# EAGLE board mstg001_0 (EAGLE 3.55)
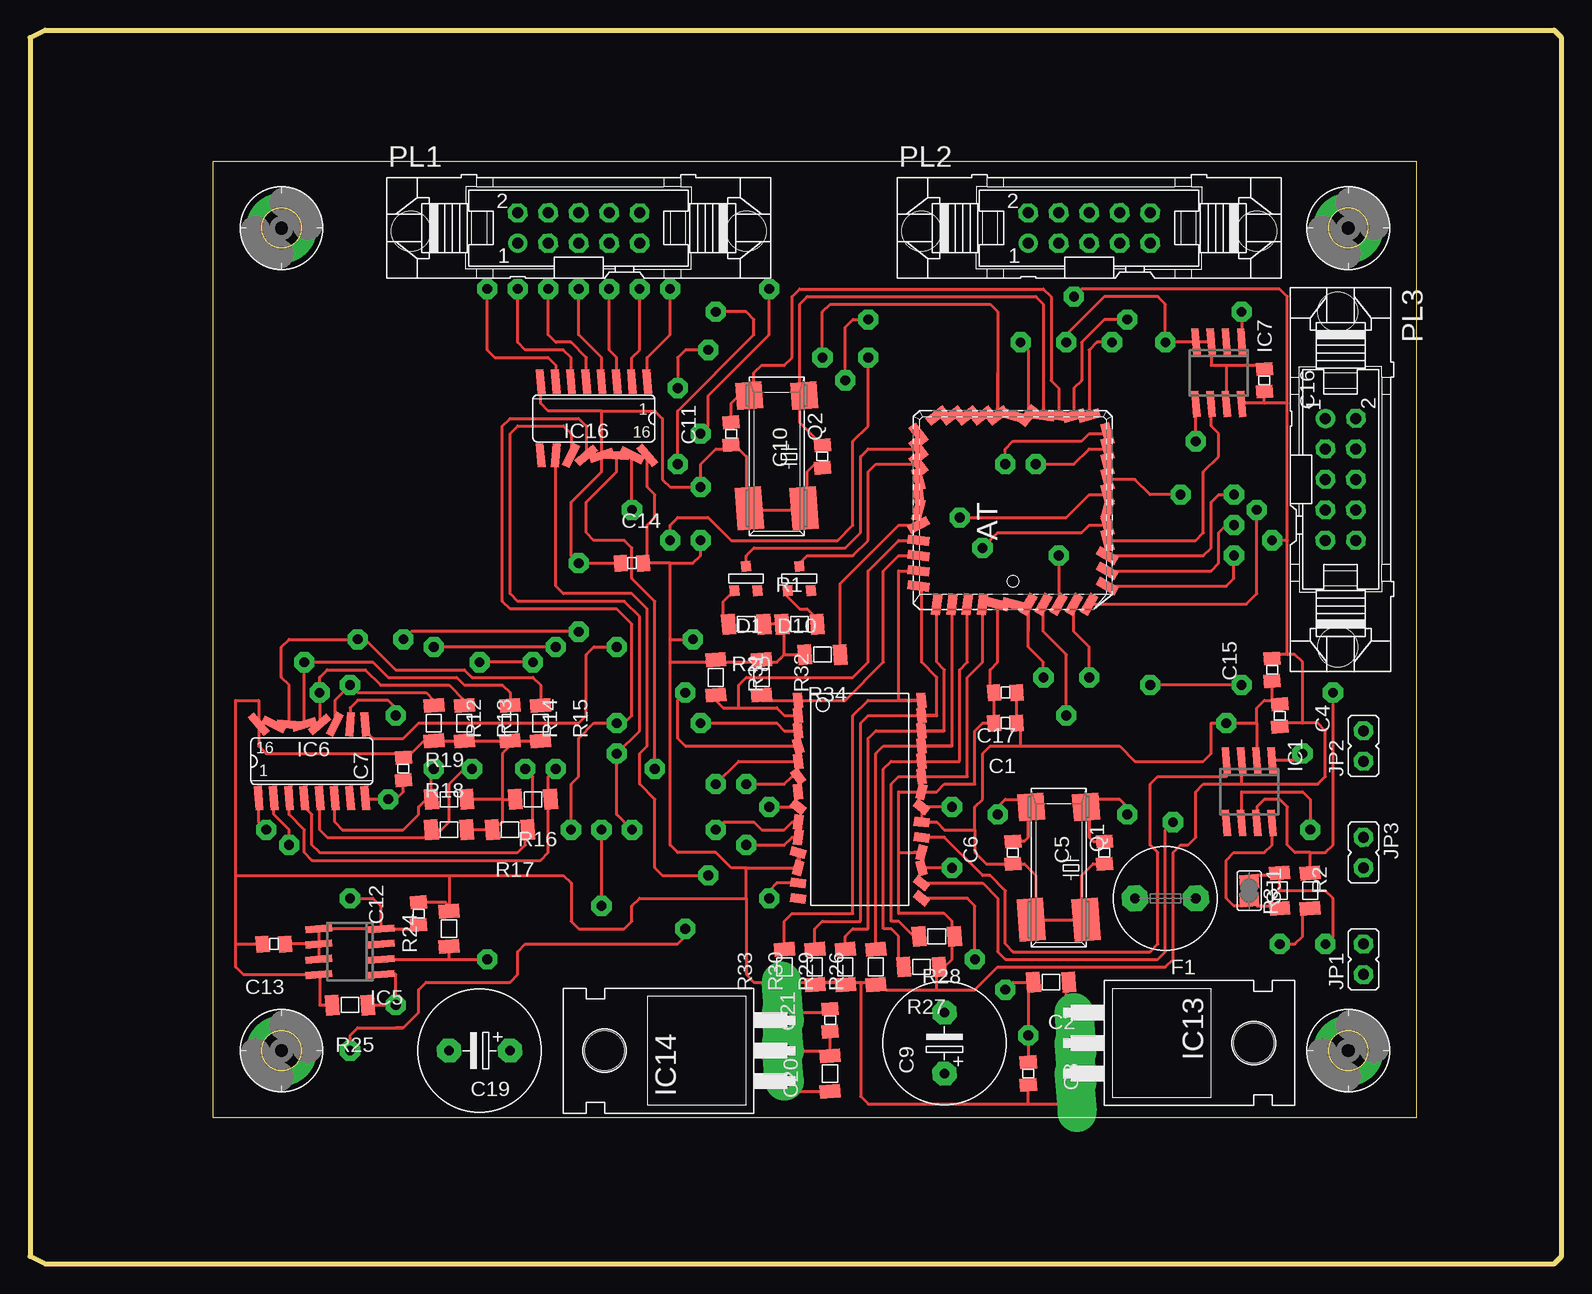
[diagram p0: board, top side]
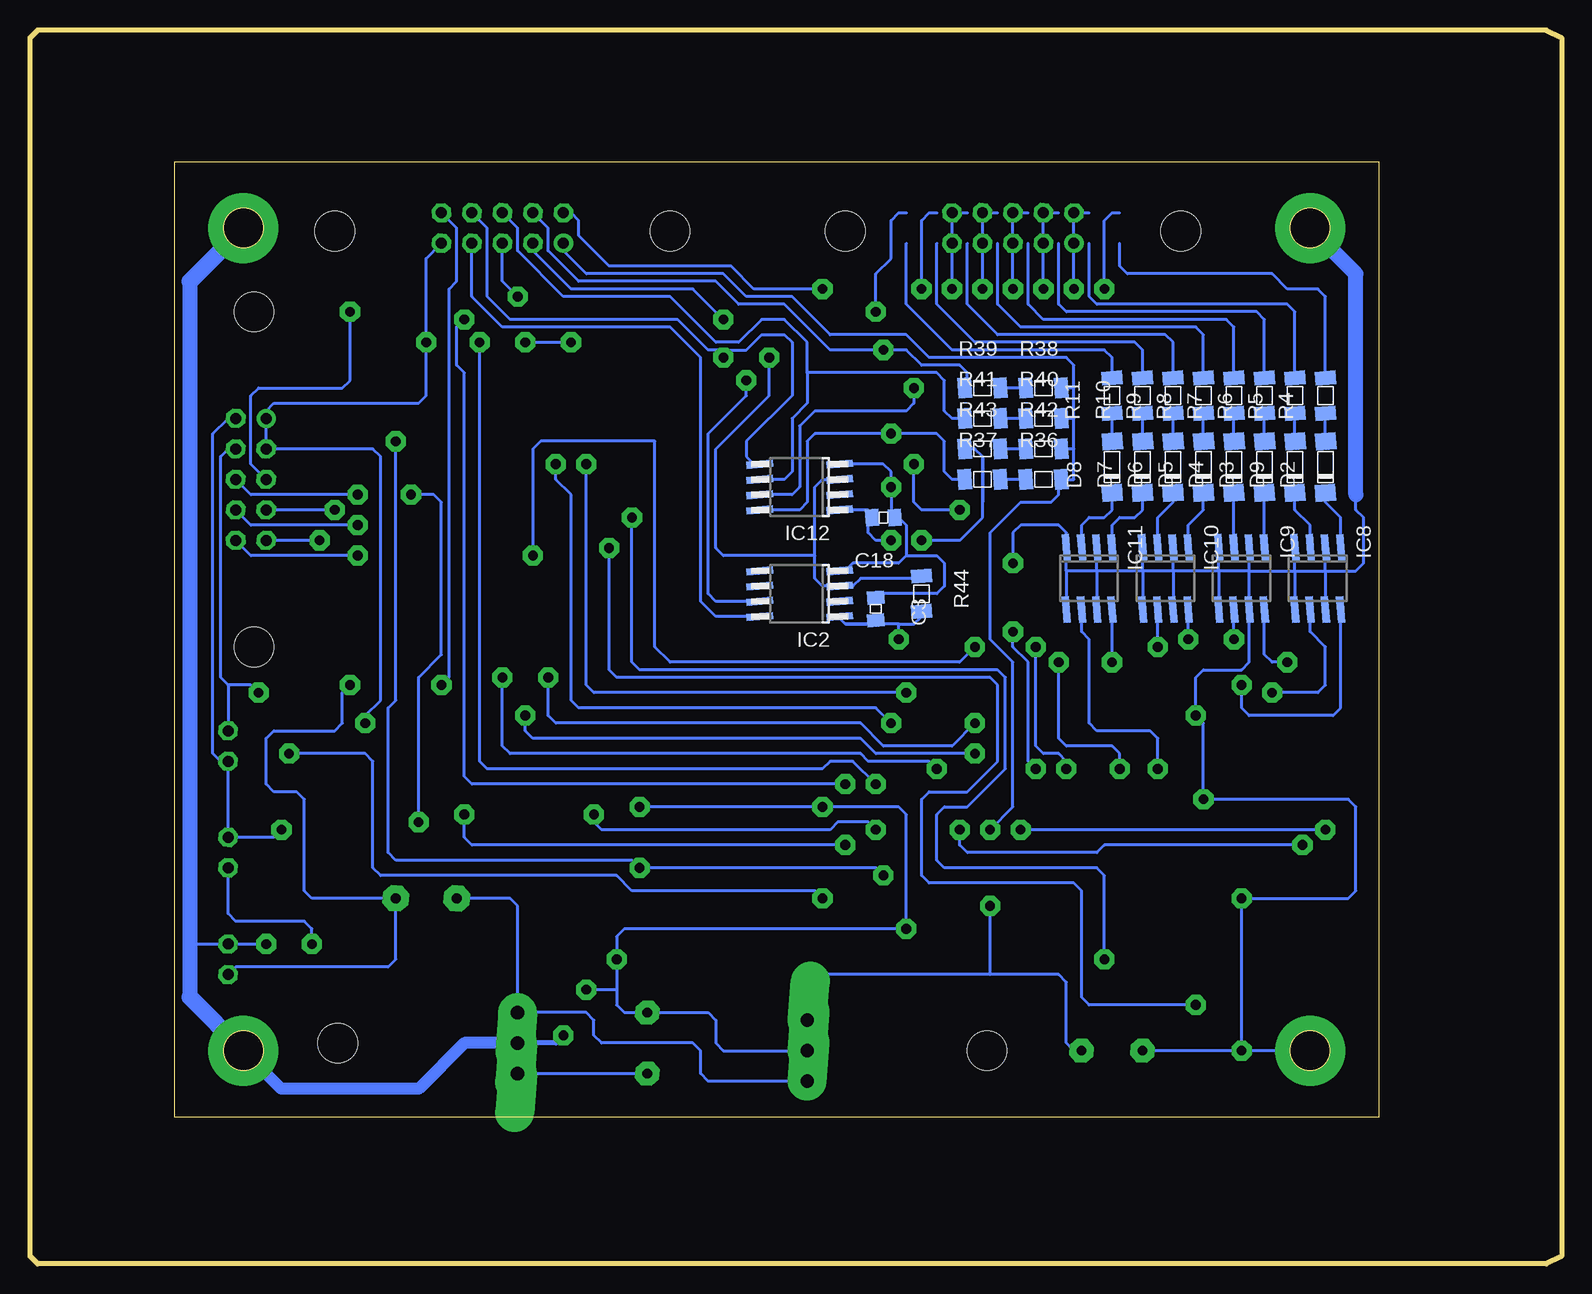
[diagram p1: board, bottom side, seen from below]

Size 127.64 x 102.87 mm. Coordinates in mm from the lower left corner, seen from the top.
Outline: 115.56,12.23 115.56,91.91 15.24,91.91 15.24,12.23 115.56,12.23
Outline: 0,0.63 1.27,0 127,0 127.64,0.63 127.64,102.23 127,102.87 1.27,102.87 0,102.23 0,0.63
Copper layers used: Top, Bottom
vRestrict: area 69.9,50.8 to 94,74.9

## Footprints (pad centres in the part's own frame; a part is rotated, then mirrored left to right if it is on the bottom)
05 = smd 1.092 x 1.397 rotated 4.4:  0.94,0 | smd 1.092 x 1.397 rotated 4.3:  -0.94,0
06 = smd 1.143 x 1.702 rotated 4.4:  1.473,0 | smd 1.143 x 1.702 rotated 4.3:  -1.473,0
-5 = drill 0.813 pad 2.007 octagon:  -2.54,0;  2.54,0
T-23 = smd 0.787 x 0.889 rotated 4.4:  0.991,1.016 | smd 0.787 x 0.889 rotated 4.3:  -0.94,1.016 | smd 0.787 x 0.889 rotated 4.5:  0.025,-1.016
D-80 = smd 1.397 x 1.702 rotated 4.4:  -2.388,0 | smd 1.397 x 1.702 rotated 4.3:  1.905,-0.025
5 = drill 0.813 pad 2.159 octagon:  -2.54,0;  2.54,0
8 = smd 0.6 x 2.2 rotated 4.4:  -0.635,-2.6 | smd 0.6 x 2.2 rotated 4.8:  -0.635,2.6 | smd 0.6 x 2.2 rotated 4.3:  -1.905,-2.6 | smd 0.6 x 2.2 rotated 4.5:  0.635,-2.6 | smd 0.6 x 2.2 rotated 4.6:  1.905,-2.6 | smd 0.6 x 2.2 rotated 4.9:  -1.905,2.6 | smd 0.6 x 2.2 rotated 4.7:  0.635,2.6;  1.905,2.6
8M = smd 0.6 x 2.2 rotated 4.4:  -0.635,-3.33 | smd 0.6 x 2.2 rotated 4.8:  -0.635,3.33 | smd 0.6 x 2.2 rotated 4.3:  -1.905,-3.33 | smd 0.6 x 2.2 rotated 4.5:  0.635,-3.33 | smd 0.6 x 2.2 rotated 4.6:  1.905,-3.33 | smd 0.6 x 2.2 rotated 4.9:  -1.905,3.33 | smd 0.6 x 2.2 rotated 4.7:  0.635,3.33;  1.905,3.33
CC-44 = smd 0.76 x 1.8 rotated 74.5: 0 -1.27,-7.86; 1 1.27,-7.86; 2 2.54,-7.86; 3 3.81,-7.86; 4 5.08,-7.86; 5 6.35,-7.86; N 2.54,7.86 | smd 1.8 x 0.76 rotated 29.5: 0 -7.86,-1.27; 1 -7.86,-2.54; 2 -7.86,-3.81; 3 -7.86,-5.08; 4 -7.86,-6.35 | smd 1.8 x 0.76 rotated 7: 0 -7.86,2.54; 1 -7.86,3.81; 2 -7.86,5.08; 3 -7.86,6.35 | smd 1.8 x 0.76 rotated 52: 0 7.86,1.27; 1 7.86,2.54; 2 7.86,3.81; 3 7.86,5.08; 4 7.86,6.35 | smd 0.76 x 1.8 rotated 7: 4 -6.35,7.86; 5 -5.08,7.86; 6 -3.81,7.86; 7 -2.54,7.86 | smd 0.76 x 1.8 rotated 52: 5 6.35,7.86; 6 5.08,7.86; 7 3.81,7.86 | smd 0.76 x 1.8 rotated 29.5: 5 -6.35,-7.86; 6 -5.08,-7.86; 7 -3.81,-7.86 | smd 1.8 x 0.76 rotated 74.5: 6 7.86,-6.35; 7 7.86,-5.08 | smd 0.76 x 1.8 rotated 275.7: /PR 1.27,7.86 | smd 1.8 x 0.76 rotated 97.7: L1 7.86,-2.54; L2 7.86,-3.81 | smd 0.76 x 1.8 rotated 28.6: VPP -1.27,7.86 | smd 0.76 x 1.8 rotated 74.7:  -2.54,-7.86 | smd 0.76 x 1.8 rotated 74.4:  0,-7.86;  0,7.86 | smd 1.8 x 0.76 rotated 74.4:  -7.86,0;  7.86,0 | smd 1.8 x 0.76 rotated 75.1:  -7.86,1.27 | smd 1.8 x 0.76 rotated 321.2:  7.86,-1.27
-28L = smd 0.762 x 1.27 rotated 321.2: 1 1.27,-5.207; 2 1.27,5.08; 3 8.89,5.08 | smd 0.762 x 1.27 rotated 75.1: 1 0,5.08; 2 5.08,5.08; 3 6.35,-5.207 | smd 0.762 x 1.27 rotated 74.7: / 6.35,5.08 | smd 0.762 x 1.27 rotated 321.4: / 7.62,5.08 | smd 0.762 x 1.27 rotated 275.7: /AS -5.08,-5.207 | smd 0.762 x 1.27 rotated 97.2: E -2.54,-5.207 | smd 0.762 x 1.27 rotated 344.3: E 5.08,-5.207 | smd 0.762 x 1.27 rotated 97.7: L1 2.54,-5.207; L2 3.81,-5.207 | smd 0.762 x 1.27 rotated 275.9: OUT 0,-5.207 | smd 0.762 x 1.27 rotated 95.7:  -7.62,-5.207;  -6.35,-5.207;  -1.27,5.08;  -2.54,5.08;  -3.81,5.08;  -5.08,5.08;  -6.35,5.08;  -7.62,5.08 | smd 0.762 x 1.27 rotated 73.4:  -3.81,-5.207 | smd 0.762 x 1.27 rotated 52.6:  -1.27,-5.207 | smd 0.762 x 1.27 rotated 187.2:  2.54,5.08;  3.81,5.08 | smd 0.762 x 1.27 rotated 187.4:  8.89,-5.207;  7.62,-5.207
16 = smd 0.66 x 2.032 rotated 4.3:  -4.445,-3.073;  3.175,3.073 | smd 0.66 x 2.032 rotated 139.3:  -4.445,3.073 | smd 0.66 x 2.032 rotated 4.4:  -3.175,-3.073 | smd 0.66 x 2.032 rotated 4.5:  -1.905,-3.073 | smd 0.66 x 2.032 rotated 116.8:  -3.175,3.073 | smd 0.66 x 2.032 rotated 94.3:  -1.905,3.073 | smd 0.66 x 2.032 rotated 4.6:  -0.635,-3.073 | smd 0.66 x 2.032 rotated 71.8:  -0.635,3.073 | smd 0.66 x 2.032 rotated 4.7:  0.635,-3.073;  1.905,-3.073 | smd 0.66 x 2.032 rotated 49.3:  0.635,3.073 | smd 0.66 x 2.032 rotated 4.8:  3.175,-3.073 | smd 0.66 x 2.032 rotated 26.8:  1.905,3.073 | smd 0.66 x 2.032 rotated 4.9:  4.445,-3.073 | smd 0.66 x 2.032 rotated 5:  4.445,3.073
220H = drill 1.118 pad 3.251 offset:  -2.54,-10.16;  0,-10.16;  2.54,-10.16 | hole 3.302: 0,4.826
1 = drill 0.914 pad 1.6 octagon:  0,-1.27;  0,1.27
3,3-P = drill 3.302 pad 5.842 round: 3 0,0
V = drill 0.914 pad 1.6 round:  -5.08,-1.27 | drill 0.914 pad 1.6 octagon:  -5.08,1.27;  -2.54,-1.27;  -2.54,1.27;  0,-1.27;  0,1.27;  2.54,-1.27;  2.54,1.27;  5.08,-1.27;  5.08,1.27 | hole 3.302: 13.97,-0.254; -13.97,-0.254
SMX = smd 3.556 x 2.184 rotated 4.4:  4.318,-2.286 | smd 3.556 x 2.184 rotated 4.5:  4.318,2.286 | smd 2.286 x 2.184 rotated 4.3:  -5.08,-2.286 | smd 2.286 x 2.184 rotated 4.6:  -5.08,2.286
 = smd 1.168 x 1.6 rotated 4.3:  -0.762,0 | smd 1.168 x 1.6 rotated 4.4:  0.762,0

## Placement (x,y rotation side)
C1  100n  [05]  81.28,45.08 180 top
C2  330n  [06]  85.09,23.49 180 top
C3  100n  [05]  57.15,54.61 270 bottom
C4  100n  [05]  104.14,45.72 270 top
C5  15pF  [05]  89.53,34.29 90 top
C6  15pF  [05]  81.92,34.29 90 top
C7  100n  [05]  31.12,41.27 90 top
C8  100n  [05]  83.19,15.88 270 top
C9  Elko 470uF  [-5]  76.2,18.41 90 top
C10  30pF +-10pF  [05]  66.04,67.31 90 top
C11  30 pF+-10pF  [05]  58.42,69.22 90 top
C12  100n  [05]  32.39,29.21 90 top
C13  100n  [05]  20.32,26.67 180 top
C14  100n  [05]  50.16,58.42 0 top
C15  100n  [05]  103.5,49.53 90 top
C16  100n  [05]  102.87,73.66 270 top
C17  100n  [05]  81.28,47.62 180 top
C18  100n  [05]  56.52,62.23 180 bottom
C19  Elko 100uF  [-5]  37.47,17.78 180 top
C20  330n  [06]  66.67,15.88 90 top
C21  100n  [05]  66.67,20.32 90 top
D1  rot  [T-23]  59.69,57.15 180 top
D2  SMD4148  [D-80]  19.68,66.67 90 bottom
D3  SMD4148  [D-80]  24.77,66.67 90 bottom
D4  SMD4148  [D-80]  27.3,66.67 90 bottom
D5  SMD4148  [D-80]  29.84,66.67 90 bottom
D6  SMD4148  [D-80]  32.39,66.67 90 bottom
D7  SMD4148  [D-80]  34.92,66.67 90 bottom
D8  SMD4148  [D-80]  37.47,66.67 90 bottom
D9  SMD4148  [D-80]  22.23,66.67 90 bottom
D10  grn  [T-23]  64.13,57.15 180 top
F1  T400mA  [5]  94.61,30.48 180 top
IC1  PCA82C250  [8]  101.6,39.37 180 top
IC2  DS2450  [8M]  63.5,55.88 90 bottom
IC3  AT89S53  [CC-44]  81.92,62.86 90 top
IC4  SJA1000  [-28L]  69.22,39.37 270 top
IC5  DS1621  [8]  26.67,26.04 90 top
IC6  74165  [16]  23.5,41.91 0 top
IC7  MAX700  [8]  99.06,74.3 180 top
IC8  ILD213T  [8]  20.32,57.15 180 bottom
IC9  ILD213T  [8]  26.67,57.15 180 bottom
IC10  ILD213T  [8]  33.02,57.15 180 bottom
IC11  ILD213T  [8]  39.37,57.15 180 bottom
IC12  DS2450  [8M]  63.5,64.77 90 bottom
IC13  78S05  [220H]  97.16,18.41 270 top
IC14  78S10  [220H]  52.7,17.78 90 top
IC16  74HC595  [16]  46.99,70.48 180 top
JP1  2-polig  [1]  111.12,25.4 0 top
JP2  2-polig  [1]  111.12,43.18 0 top
JP3  2-polig  [1]  111.12,34.29 180 top
PAD5  BO3,3P  [3,3-P]  109.86,86.36 0 top
PAD6  BO3,3P  [3,3-P]  20.95,86.36 0 top
PAD7  BO3,3P  [3,3-P]  20.95,17.78 0 top
PAD8  BO3,3P  [3,3-P]  109.86,17.78 0 top
PL1  16V  [V]  45.72,86.36 0 top
PL2  10V  [V]  88.27,86.36 0 top
PL3  10V  [V]  109.22,65.41 270 top
Q1  16MHZ  [SMX]  85.72,33.02 270 top
Q2  16MHZ  [SMX]  62.23,67.31 270 top
R1  2k7  [06]  64.13,53.34 0 top
R2  47k  [06]  104.14,31.11 270 top
R3  120R  [06]  106.68,31.11 90 top
R4  2k7  [06]  19.68,72.39 90 bottom
R5  2k7  [06]  22.23,72.39 90 bottom
R6  2k7  [06]  24.77,72.39 90 bottom
R7  2k7  [06]  27.3,72.39 90 bottom
R8  2k7  [06]  29.84,72.39 90 bottom
R9  2k7  [06]  32.39,72.39 90 bottom
R10  2k7  [06]  34.92,72.39 90 bottom
R11  2k7  [06]  37.47,72.39 90 bottom
R12  4k7  [06]  33.66,45.08 270 top
R13  4k7  [06]  36.2,45.08 270 top
R14  4k7  [06]  40,45.08 270 top
R15  4k7  [06]  42.55,45.08 270 top
R16  4k7  [06]  41.91,38.73 180 top
R17  4k7  [06]  40,36.2 180 top
R18  4k7  [06]  34.92,36.2 0 top
R19  4k7  [06]  34.92,38.73 0 top
R20  2k7  [06]  59.69,53.34 180 top
R24  1k  [06]  34.92,27.94 90 top
R25  1k  [06]  26.67,21.59 180 top
R26  4k7  [06]  70.48,24.77 90 top
R27  4k7  [06]  74.3,24.77 180 top
R28  4k7  [06]  75.56,27.3 180 top
R29  4k7  [06]  67.94,24.77 90 top
R30  4k7  [06]  65.41,24.77 90 top
R31  4k7  [06]  57.15,48.89 270 top
R32  4k7  [06]  60.96,48.89 270 top
R33  4k7  [06]  62.87,24.77 90 top
R34  4k7  [06]  66.04,50.8 180 top
R36  tbd  [06]  43.18,65.41 0 bottom
R37  0R  [06]  48.26,65.41 0 bottom
R38  tbd  [06]  43.18,73.03 0 bottom
R39  0R  [06]  48.26,73.03 0 bottom
R40  tbd  [06]  43.18,70.48 0 bottom
R41  tbd  [06]  48.26,70.48 0 bottom
R42  tbd  [06]  43.18,67.94 0 bottom
R43  tbd  [06]  48.26,67.94 0 bottom
R44  5.0 k  [06]  53.34,55.88 270 bottom
SJ1  SJ  []  101.6,31.11 270 top

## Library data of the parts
C1-C8 C10-C18 C20 C21 D1-D10 R1-R20 R24-R34 R36-R44 = smd
C9 C19 = discrete
F1 = fuse
IC1-IC5 IC7-IC12 = andit4at
IC6 IC16 = andi74sm
IC13 IC14 = linear
JP1-JP3 = jumps
PAD5-PAD8 = holes
PL1-PL3 = pinh-v
Q1 Q2 = quartz
SJ1 = jumper

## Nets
+5V: C1. C3. C4. C7. C8. C9. C12. C13. C14. C15. C16. C17. C18. IC1. IC2. IC3. IC4.1 IC4.2 IC4.3 IC4.E IC5. IC6. IC7. IC12. IC13. IC16. PL2. PL3. R1. R12. R13. R14. R15. R16. R17. R18. R19. R20. R24. R25. R26. R27. R28. R29. R30. R31. R32. R33. R34. R44.
GND: C1. C2. C3. C4. C5. C6. C7. C8. C9. C10. C11. C12. C13. C14. C15. C16. C17. C18. C19. C20. C21. IC1. IC2. IC3. IC4. IC4.1 IC4.2 IC4.3 IC5. IC6. IC7. IC8. IC9. IC10. IC11. IC12. IC13. IC14. IC16. JP1. PAD5.3 PAD6.3 PAD7.3 PAD8.3 PL2. PL3. Q1. Q2. R2. SJ1.
N$1: IC3.0 IC4. R28.
N$2: IC3.1 IC4. R27.
N$3: IC3.5 IC4. R33.
N$4: IC3.VPP R34.
N$5: IC3.7 IC4. R31.
N$6: C2. C20. F1. IC13. IC14.
N$7: IC12. PL2. R37.
N$9: IC1. IC4.
N$11: C11. IC3.L2 Q2.
N$12: C19. C21. IC14. PL2. R36. R38. R40. R42.
N$15: IC16. PL1.
N$16: IC1. JP2. PL3. R3.
N$18: PL1. R5.
N$19: IC2. IC3.0 IC12. R44.
N$20: IC16. PL1.
N$21: PL1. R4.
N$22: D10. IC3.7
N$23: D1. IC3.6
N$24: D10. R1.
N$26: PL1. R6.
N$27: D9. R5.
N$28: D2. R4.
N$29: IC3.0 IC6. IC16.
N$30: IC3.1 IC6. IC16.
N$31: D3. R6.
N$32: D4. R7.
N$33: D5. R8.
N$34: IC3.2 IC6.
N$35: D6. R9.
N$36: IC1. JP2. JP3. PL3.
N$37: IC3.4 IC4./AS
N$38: IC3.6 PL3.
N$39: IC3.5 PL3.
N$40: IC3.7 PL3.
N$41: IC3. IC7.
N$42: IC3.5 IC4.
N$43: IC16. PL1.
N$44: IC3.1 IC5. R24.
N$45: IC3.0 IC5. R25.
N$46: IC3.6 IC4.E
N$47: IC3.7 IC4.
N$48: IC3.2 IC4./
N$49: IC7. PL3.
N$50: IC4./ IC7. IC16.
N$51: C5. IC4.L2 Q1.
N$52: C6. IC4.L1 Q1.
N$54: D1. R20.
N$55: IC1. IC4.
N$56: R36. R37.
N$57: R38. R39.
N$58: R40. R41.
N$59: R42. R43.
N$60: IC2. PL2.
N$61: F1. JP1. PL2.
N$63: IC1. R2. SJ1.
N$64: D7. R10.
N$65: JP3. R3.
N$67: D8. R11.
N$68: D9. IC8.
N$69: IC12. PL2. R39.
N$70: C10. IC3.L1 Q2.
N$71: D3. IC9.
N$72: D4. IC9.
N$73: D5. IC10.
N$74: D6. IC10.
N$75: D7. IC11.
N$76: IC6. IC8. R12.
N$77: D8. IC11.
N$78: IC2. PL2.
N$79: IC3.4 PL3.
N$80: IC6. IC8. R13.
N$81: IC12. PL2. R41.
N$82: D2. IC8.
N$83: IC6. IC9. R14.
N$84: IC16. PL1.
N$85: IC6. IC9. R15.
N$86: IC12. PL2. R43.
N$87: IC6. IC10. R16.
N$88: IC16. PL1.
N$89: IC6. IC10. R17.
N$90: IC16. PL1.
N$91: IC6. IC11. R18.
N$92: IC16. PL1.
N$93: IC6. IC11. R19.
N$94: IC16. PL1.
N$95: PL1. R11.
N$96: PL1. R8.
N$98: IC3.3 IC16.
N$102: IC3.2 IC4. R26.
N$104: IC3.3 IC4. R29.
N$105: IC3.4 IC4. R30.
N$106: IC3.6 IC4. R32.
N$108: PL1. R7.
N$110: PL1. R9.
N$112: PL1. R10.

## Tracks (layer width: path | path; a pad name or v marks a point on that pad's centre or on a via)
+5V  (via drill 0.81 pad 1.68)
  Top 0.254: 17.14,32.38 17.14,46.99 19.05,46.99 19.05,44.98 19.05,43.18 19.68,42.55 31.12,42.55 | 102.87,71.75 102.87,72.72 102.87,73.03 | 104.78,71.75 104.78,80.64 104.14,81.28 87.63,81.28 v87,80.64 | 104.78,71.75 102.87,71.75 | 104.78,60.33 104.78,71.75 | 65.41,23.49 63.07,23.49 R33. 62.87,23.49 60.33,23.49 59.69,24.13 59.69,30.48 | 67.94,23.49 R29. 68.15,23.49 70.48,23.49 R26. 70.69,23.49 71.32,22.86 75.56,22.86 | R30. 65.61,23.49 66.04,23.49 | 67.94,23.49 66.04,23.49 | 73.66,34.29 74.3,34.29 72.39,34.29 | 64.13,33.15 IC4.3 | 64.13,33.15 64.13,34.29 | 72.39,34.29 72.39,39.37 IC4.1 75.56,39.37 76.2,40 78.74,40 78.74,44.45 79.38,45.08 80.34,45.08 80.01,45.08 80.34,45.42 80.34,47.62 80.01,47.62 80.01,49.53 80.64,50.17 80.64,55 | 72.39,34.29 72.39,29.21 76.2,29.21 76.84,28.57 76.84,27.3 | 77.47,27.3 R28. 76.84,27.3 | 40.21,43.61 42.55,43.61 42.55,43.81 | 40.21,43.61 40,43.81 40,43.61 36.4,43.61 36.2,43.81 36.2,43.61 33.86,43.61 33.66,43.81 33.66,43.61 32.82,43.61 31.75,42.55 31.12,42.55 | 67.94,23.49 69.22,23.49 69.22,13.97 69.85,13.33 83.19,13.33 | 65.41,23.49 67.94,23.49 | IC4.E 64.01,33.15 64.13,33.02 | 59.69,33.02 64.13,33.02 | 103.5,50.47 103.5,50.8 104.78,50.8 | 104.14,44.78 104.14,45.08 106.05,45.08 | 106.05,45.08 107.31,45.08 107.95,44.45 107.95,40.64 107.31,40 100.97,40 | 106.05,45.08 106.05,50.17 105.41,50.8 104.78,50.8 | R32. 60.96,50.17 57.15,50.17 | 53.34,50.17 53.34,34.92 53.98,34.29 57.15,34.29 58.42,33.02 59.69,33.02 | 100.97,40 97.79,40 97.16,39.37 97.16,35.56 96.52,34.92 95.89,34.92 95.25,34.29 95.25,25.4 94.61,24.77 80.64,24.77 78.74,22.86 75.56,22.86
  Top 0.254: 75.56,22.86 75.56,24.77 R27. 76.2,24.77 76.84,25.4 76.84,27.3 | 53.34,50.17 57.15,50.17 | 57.15,50.8 R31. 57.15,50.17 | 65.41,23.49 66.04,23.49 | 64.13,33.02 64.13,33.15 | 40.21,43.61 40.21,43.38 39.37,42.55 39.37,38.73 | 40.64,38.73 40.44,38.73 39.37,38.73 | 39.37,38.73 36.4,38.73 | 34.92,29.21 34.92,29.41 34.92,29.84 | 100.97,40 100.97,41.97 | 32.39,30.15 34.62,30.15 34.92,29.84 | 104.78,50.8 104.78,60.33 | 104.78,60.33 v103.5,60.33 | 62.87,53.34 R1. R20. | 62.87,50.8 62.43,50.37 | 100.97,71.75 100.97,72.39 | 100.97,71.12 100.97,71.69 100.97,71.75 | 102.87,71.75 100.97,71.75 | 34.92,32.38 34.92,29.84 | 17.14,32.38 34.92,32.38 | 17.14,26.67 17.14,24.77 17.78,24.13 24.07,24.13 24.13,24.13 24.13,21.59 25.2,21.59 | 19.68,26.67 19.38,26.67 17.14,26.67 | 17.14,26.67 17.14,32.38 | 53.34,58.42 55.24,58.42 55.88,59.05 v55.88,60.33 | 53.34,52.07 53.34,58.42 | 62.87,50.8 64.57,50.8 | 83.19,13.33 83.19,14.93 | 83.19,13.33 86.36,13.33 87,13.97 IC13. | 51.44,67.41 51.44,64.77 52.07,64.14 52.07,62.23 51.44,61.59 51.44,58.42 | 51.44,58.42 51.1,58.42 | 53.34,58.42 51.44,58.42 | 34.92,32.38 44.45,32.38 45.09,31.75 45.09,28.57 45.72,27.94 49.53,27.94 50.16,28.57 50.16,29.84 50.8,30.48 59.69,30.48 | 59.69,30.48 59.69,33.02 | 31.12,42.55 31.12,42.22 | 39.37,38.73 39.37,36.83 38.73,36.2 | 38.73,36.2 38.53,36.2 | 38.73,36.2 36.4,36.2 | R20. 60.96,53.34 | 62.87,53.34 R20. | 62.87,50.8 62.87,53.34 | 62.87,50.8 62.23,50.17 53.34,50.17 | 53.34,50.17 53.34,52.07 | 53.34,52.07 v55.24,52.07
  Bottom 0.254: v103.5,60.33 107.95,60.33 | 88.27,85.09 88.27,81.92 v87,80.64 | 60.17,53.97 60.17,53.82 59.69,53.34 | 59.69,53.34 57.78,53.34 57.15,53.97 57.15,53.67 57.15,53.34 | 53.34,54.41 53.34,53.97 53.98,53.34 55.24,53.34 | 85.72,15.88 IC13. 76.2,15.88 | v55.88,60.33 57.15,60.33 57.78,60.96 57.78,62.23 57.45,62.23 57.15,62.23 57.78,62.86 60.17,62.86 | 57.15,53.34 59.69,53.34 | 55.24,53.34 57.15,53.34 | v55.24,52.07 55.24,53.34
GND  (via drill 0.81 pad 1.68)
  Top 0.254: v61.59,38.1 64.01,38.1 | v76.84,38.1 IC4.2 74.3,36.83 75.56,36.83 76.2,36.2 78.74,36.2 | v78.74,25.4 78.74,29.84 78.1,30.48 74.3,30.48 | 104.14,32.38 104.14,31.11 107.95,31.11 108.58,30.48 108.58,27.3 v107.95,26.67 | 104.14,32.38 102.23,32.38 101.6,31.75 101.6,31.88 | C10. 66.04,66.67 65.41,66.67 64.77,66.04 64.77,62.86 | 64.77,62.86 64.77,62.23 | 59.69,62.86 64.39,62.86 64.52,62.99 64.64,62.99 64.77,62.86 | 59.94,62.99 59.82,62.86 59.69,62.86 | 59.69,62.86 59.69,67.31 59.05,67.94 | 88.01,28.7 83.44,28.7 83.69,28.7 83.82,28.57 83.82,32.38 82.86,33.35 82.22,33.35 81.92,33.66 C6. 79.68,33.35 78.74,34.29 78.74,36.2 | 88.01,28.7 88.14,28.7 88.27,28.57 | 88.01,28.7 87.76,28.7 87.63,28.57 87.63,32.38 88.59,33.35 89.23,33.35 89.53,33.66 C5. | 102.23,45.08 v99.69,45.08 98.42,45.08 98.42,42.55 97.79,41.91 92.08,41.91 90.81,43.18 82.55,43.18 | 102.23,45.08 102.23,46.36 102.87,46.99 103.5,46.99 | 82.55,45.08 82.22,45.42 82.22,47.32 81.92,47.62 C17. | 78.74,36.2 78.74,38.1 79.38,38.73 79.38,42.55 80.01,43.18 82.55,43.18 | 82.55,43.18 82.55,45.08 | 42.55,73.56 42.55,71.75 43.18,71.12 47.62,71.12 | 47.62,71.12 47.62,67.41 47.62,66.04 45.09,63.5 45.09,59.05 v45.72,58.42 C14. | 47.62,71.12 52.07,71.12 52.7,70.48 52.7,65.41 53.34,64.77 v55.88,64.77 55.88,66.67 57.15,67.94 59.05,67.94 | 59.05,67.94 58.42,67.94 C11. 58.42,68.58 | 27.94,38.84 27.94,38.73 v29.84,38.73 30.48,38.73 31.12,39.37 C7. | 26.67,44.98 26.67,46.36 27.3,46.99 29.84,46.99 30.48,46.36 v30.48,45.72 | 24.07,25.4 24.07,26.61 24.13,26.67 | 24.13,26.67 24.07,26.67 C13. 20.95,26.67 | 24.13,26.67 24.07,26.73 IC5. 29.21,27.94
  Top 0.254: 29.21,27.94 29.27,27.94 31.75,27.94 32.39,28.57 C12. 32.39,27.94 29.21,27.94 | 81.92,45.08 C1. 82.55,45.08 | 103.5,46.99 C15. | 103.5,46.99 104.14,46.36 C4. | 102.23,41.91 102.23,41.97 102.23,45.08 | 83.19,16.51 C8. v83.19,19.05 83.19,22.86 83.82,23.49 83.19,23.49 | 66.67,17.14 66.67,17.35 66.67,17.78 | 66.67,17.78 C21. | 62.87,17.78 66.67,17.78 | 99.69,74.93 98.42,74.93 98.42,76.84 | 98.42,76.84 98.36,76.89 97.16,76.89 95.31,76.89 95.25,76.84 v94.61,76.84 94.61,80.01 93.98,80.64 89.53,80.64 86.36,77.47 v86.36,76.84 | 99.69,74.93 99.69,71.69 | C16. 102.87,74.3 102.23,74.93 99.69,74.93 | 98.42,76.84 98.42,76.89 | 104.14,32.38 R2. | v26.67,30.48 28.57,30.48 29.21,29.84 29.21,27.94 | 83.19,70.72 83.19,76.2 v82.55,76.84 | 83.19,23.49 81.92,23.49 v81.28,22.86 | 83.19,23.49 83.62,23.49 | v54.61,27.94 54.61,27.3 53.98,26.67 41.27,26.67 40.64,26.04 40.64,24.13 40,23.49 33.02,23.49 32.39,22.86 32.39,20.95 31.12,19.68 | 31.12,19.68 30.48,19.68 | 31.12,19.68 27.3,19.68 26.67,19.05 v26.67,17.78
  Bottom 0.254: v76.84,38.1 v61.59,38.1 55.24,38.1 54.61,37.47 v54.61,27.94 78.1,27.94 78.74,27.3 v78.74,25.4 78.74,22.86 | v107.95,26.67 JP1. 114.3,26.67 | 22.23,57.78 22.23,59.75 | 26.04,57.78 26.04,59.75 | 28.57,57.78 28.57,59.75 | 32.39,57.78 32.39,59.75 | 34.92,57.78 34.92,59.75 | 38.73,57.78 38.73,59.75 | 41.27,57.78 41.27,59.75 41.27,60.96 41.91,61.59 45.09,61.59 45.72,60.96 v45.72,58.42 | 19.68,57.78 19.68,54.55 | 22.23,57.78 19.68,57.78 | 22.23,57.78 IC8. | 26.04,57.78 22.23,57.78 | 26.04,57.78 26.04,54.55 26.04,50.17 26.67,49.53 29.84,49.53 30.48,48.89 v30.48,45.72 29.84,45.08 v29.84,38.73 17.78,38.73 17.14,38.1 17.14,31.11 17.78,30.48 v26.67,30.48 v26.67,17.78 | 26.04,57.78 28.57,57.78 | 28.57,57.78 IC9. | 28.57,57.78 32.39,57.78 | 32.39,57.78 32.39,54.55 | 32.39,57.78 34.92,57.78 | 34.92,57.78 IC10. | 34.92,57.78 38.73,57.78 | 38.73,57.78 38.73,54.55 | 38.73,57.78 41.27,57.78 | 41.27,57.78 IC11. | 78.74,22.86 78.74,21.59 78.1,20.95 C9. 71.12,20.95 70.48,20.32 70.48,18.41 69.85,17.78 62.87,17.78 | 93.34,85.09 94.61,83.82 v94.61,76.84 94.61,72.39 95.25,71.75 107.31,71.75 107.95,71.12 107.95,70.48 107.95,67.94 99.06,67.94 98.42,67.31 98.42,46.99 99.69,45.72 v99.69,45.08 | PAD7.3 v26.67,17.78 | 60.17,57.78 59.69,57.78 59.05,58.42 55.24,58.42 54.61,59.05 | 60.17,66.67 56.52,66.67 55.88,66.04 v55.88,64.77 55.88,62.23 C18. 55.24,62.23 54.61,61.59 54.61,59.05 | 60.17,66.67 60.33,66.67 | C3. 57.15,55.88 52.07,55.88 51.44,56.52 51.44,58.42 52.07,59.05 54.61,59.05 | 19.68,57.78 19.68,59.75 | 19.68,57.78 17.14,57.78 16.51,58.42 16.51,62.23 17.14,62.86 17.14,64.14 | v86.36,76.84 v82.55,76.84
  Bottom 0.254: 78.74,22.86 v81.28,22.86 | 60.17,66.67 60.17,66.52 | v26.67,17.78 C19.
  Bottom 0.406: v83.19,19.05 83.82,18.41 87,18.41
  Bottom 1.016: 87,18.41 91.44,18.41 95.25,14.6 106.68,14.6 PAD8.3
  Bottom 1.27: 114.3,81.92 114.3,26.67 114.3,22.23 | PAD6.3 17.14,82.55 17.14,64.14
  Bottom 1.422: PAD8.3 114.3,22.23 | 114.3,81.92 PAD5.3
N$1
  Top 0.254: 79.38,55 79.38,50.17 78.1,48.89 78.1,40.64 74.3,40.64 72.39,40.64 71.75,40 71.75,28.57 72.39,28.57 73.66,27.3 74.09,27.3
N$2
  Top 0.254: 78.1,55 78.1,50.17 77.47,49.53 77.47,41.91 74.3,41.91 71.75,41.91 71.12,41.27 71.12,27.94 71.75,27.94 72.39,27.3 72.39,25.4 73.03,24.77 72.82,24.77
N$3
  Top 0.254: 74.06,57.78 72.39,57.78 72.39,46.99 IC4. 69.85,46.99 68.58,45.72 68.58,29.21 63.5,29.21 62.87,28.57 62.87,26.24 62.87,26.04
N$4
  Top 0.254: R34. 67.51,56.72 72.39,61.59 IC3.VPP 74.3,61.59
N$5
  Top 0.254: 74.06,60.33 72.39,60.33 69.85,57.78 69.85,50.17 68.58,48.89 59.69,48.89 59.05,48.26 59.05,46.36 | 59.05,46.36 62.23,46.36 62.87,45.72 64.01,45.72 64.13,45.72 | 57.15,47.42 57.15,46.99 57.78,46.36 59.05,46.36
N$6
  Top 0.254: 86.36,20.95 87,20.95 86.36,21.59 86.36,23.49 C2. | C20. 63.7,14.4 62.87,15.24
  Bottom 0.254: F1. 87.63,30.48 87,29.84 87,20.95 | 62.87,15.24 71.12,15.24 71.75,15.88 71.75,17.78 72.39,18.41 80.01,18.41 80.64,19.05 80.64,20.32 81.28,20.95 87,20.95 | 87,20.95 86.36,20.95
N$7  (via drill 0.81 pad 1.68)
  Top 0.254: v55.88,69.22 56.52,69.85 56.52,72.39 61.59,77.47 v61.59,81.28
  Bottom 0.254: 83.19,87.63 82.55,87.63 81.92,87 81.92,85.73 79.38,83.19 69.22,83.19 67.31,81.28 v61.59,81.28 | 49.53,65.41 R37. 50.8,65.41 51.44,66.04 51.44,68.58 52.07,69.22 v55.88,69.22 62.23,69.22 62.87,68.58 62.87,63.5 63.5,62.86 66.83,62.86
N$9  (via drill 0.81 pad 1.68)
  Top 0.254: 103.5,41.97 105.47,41.97 v106.05,42.55 | 64.01,31.75 62.23,31.75 61.59,31.11 v61.59,30.48
  Bottom 0.254: v106.05,42.55 99.69,42.55 99.06,41.91 99.06,33.02 98.42,32.38 78.74,32.38 77.47,31.11 62.23,31.11 v61.59,30.48
N$11
  Top 0.254: 59.05,72.39 59.94,72.39 | 59.05,72.39 60.33,73.66 60.33,74.3 60.96,74.93 62.87,74.93 63.5,75.56 63.5,80.64 64.13,81.28 84.45,81.28 85.09,80.64 85.09,73.66 85.72,73.03 IC3.L2 | 59.05,72.39 58.42,71.75 58.42,70.16 58.42,69.85
N$12  (via drill 0.81 pad 1.68)
  Top 0.254: IC14. 63.5,20.95 66.04,20.95 66.67,21.59 66.67,21.26 | v47.62,29.84 v47.62,36.2
  Bottom 0.254: 40,17.78 40.64,17.78 41.27,18.41 41.27,23.49 41.91,24.13 47.62,24.13 | 47.62,24.13 61.59,24.13 62.87,22.86 IC14. | 40.64,70.48 40.64,73.03 | 83.19,85.09 83.19,84.45 81.28,82.55 69.85,82.55 67.94,80.64 64.13,80.64 60.96,77.47 54.61,77.47 52.7,75.56 41.27,75.56 40.64,74.93 40.64,73.03 | 40.64,70.48 41.71,70.48 | 40.64,67.94 40.64,70.48 | 41.91,67.94 41.71,67.94 40.64,67.94 | 40.64,67.94 40.64,65.41 41.71,65.41 41.91,65.41 41.91,64.14 42.55,63.5 45.09,63.5 47.62,60.96 47.62,52.07 45.72,50.17 45.72,38.1 v47.62,36.2 | 47.62,24.13 v47.62,29.84 | 40.64,73.03 41.71,73.03
N$15  (via drill 0.81 pad 1.68)
  Top 0.254: v57.15,79.38 59.69,79.38 60.33,78.74 60.33,77.47 53.98,71.12 v53.98,66.67 | v50.16,62.86 50.16,67.41
  Bottom 0.254: 54.61,87.63 55.24,87.63 55.88,87 55.88,83.82 57.15,82.55 v57.15,79.38 | v53.98,66.67 53.98,63.5 53.34,62.86 v50.16,62.86
N$16  (via drill 0.81 pad 1.68)
  Top 0.254: 106.68,32.38 106.68,32.59 106.68,34.29 | 106.68,34.29 107.95,34.29 108.58,34.92 v108.58,47.62 | 106.68,34.29 105.41,34.29 104.78,34.92 104.78,38.1 104.14,38.73 102.87,38.73 102.23,38.1 102.23,36.77
  Bottom 0.254: 110.49,67.94 111.12,67.94 111.76,67.31 111.76,48.89 111.12,48.26 | 111.12,48.26 JP2. | v108.58,47.62 109.22,48.26 111.12,48.26
N$18
  Bottom 0.254: 39.37,85.09 39.37,80.64 38.73,80.01 22.86,80.01 22.23,79.38 22.23,73.86 22.23,73.66
N$19  (via drill 0.81 pad 1.68)
  Top 0.254: 80.64,74.3 IC3.0 80.64,79.38 80.01,80.01 66.67,80.01 66.04,79.38 v66.04,75.56
  Bottom 0.254: R44. 53.34,57.15 58.42,57.15 59.05,56.52 60.17,56.52 61.59,56.52 62.23,57.15 62.23,59.05 | 59.69,65.41 60.17,65.41 61.59,65.41 62.23,64.77 62.23,59.05 | 62.23,59.05 69.85,59.05 70.48,59.69 70.48,67.94 66.04,72.39 v66.04,75.56
N$20  (via drill 0.81 pad 1.68)
  Top 0.254: 51.44,73.56 51.44,75.56 53.34,77.47 v53.34,81.28
  Bottom 0.254: 52.07,87.63 52.7,87.63 53.34,87 v53.34,81.28
N$21
  Bottom 0.254: 36.83,85.09 36.83,83.19 36.2,82.55 24.13,82.55 22.86,81.28 20.32,81.28 19.68,80.64 19.68,73.86 19.68,73.66
N$22
  Top 0.254: D10. 64.11,58.39 64.77,59.05 68.58,59.05 69.85,60.33 69.85,66.04 70.48,66.67 74.06,66.67 74.3,66.67
N$23
  Top 0.254: 74.06,67.94 69.85,67.94 69.22,67.31 69.22,60.96 67.94,59.69 60.33,59.69 59.69,59.05 59.69,58.42 59.66,58.39 D1.
N$24
  Top 0.254: 63.14,56.13 63.14,55.6 64.13,54.61 64.77,54.61 65.41,53.97 65.41,53.34 65.61,53.34
N$26
  Bottom 0.254: 41.91,85.09 41.91,80.01 41.27,79.38 25.4,79.38 24.77,78.74 24.77,73.86 24.77,73.66
N$27
  Bottom 0.254: D9. 22.23,68.58 R5.
N$28
  Bottom 0.254: D2. 19.68,68.58 R4.
N$29  (via drill 0.81 pad 1.68)
  Top 0.254: 19.05,38.84 19.05,36.83 v19.68,36.2 | 83.19,52.7 83.19,55 83.19,51.44 84.45,50.17 v84.45,48.89 | v45.09,36.2 45.09,40 45.72,40.64 45.72,43.81 46.99,45.08 v48.9,45.08 49.53,45.08 50.16,45.72 50.16,53.34 48.9,54.61 40,54.61 39.37,55.25 39.37,69.85 40,70.48 45.72,70.48 46.36,69.85 46.36,67.41 46.36,67.31
  Bottom 0.254: v19.68,36.2 v45.09,36.2 | v84.45,48.89 84.45,45.72 83.82,45.08 58.42,45.08 56.52,43.18 50.8,43.18 v48.9,45.08
N$30  (via drill 0.81 pad 1.68)
  Top 0.254: v21.59,34.92 21.59,36.2 20.32,37.47 20.32,38.84 | v86.36,45.72 86.36,50.8 84.45,52.7 84.45,55 | v50.16,36.2 48.9,37.47 v48.9,42.55 50.8,44.45 50.8,53.97 49.53,55.25 40.64,55.25 40,55.88 40,69.22 40.64,69.85 44.45,69.85 45.09,69.22 45.09,67.41
  Bottom 0.254: v21.59,34.92 38.1,34.92 38.73,34.29 49.53,34.29 50.16,34.92 v50.16,36.2 | v86.36,45.72 86.36,44.45 85.72,43.81 58.42,43.81 57.15,42.55 v48.9,42.55
N$31
  Bottom 0.254: D3. 24.77,68.58 R6.
N$32
  Bottom 0.254: D4. 27.3,68.58 R7.
N$33
  Bottom 0.254: D5. 29.84,68.58 R8.
N$34  (via drill 0.81 pad 1.68)
  Top 0.254: IC6. 27.94,44.45 28.57,43.81 31.12,43.81 32.39,45.08 45.72,45.08 46.36,45.72 46.36,50.8 46.99,51.44 v48.9,51.44 | v85.72,59.05 85.72,55 v85.72,59.05
  Bottom 0.254: v85.72,59.05 85.72,67.94 85.09,68.58 75.56,68.58 75.56,51.44 74.3,50.17 50.16,50.17 v48.9,51.44
N$35
  Bottom 0.254: D6. 32.39,68.58 R9.
N$36  (via drill 0.81 pad 1.68)
  Top 0.254: 100.97,36.77 100.97,39.37 106.05,39.37 106.68,38.73 v106.68,36.2
  Bottom 0.254: v106.68,36.2 107.31,35.56 111.12,35.56 111.12,41.91 111.76,41.91 112.39,42.55 112.39,69.22 111.12,70.48 110.49,70.48
N$37  (via drill 0.81 pad 1.68)
  Top 0.254: 89.78,67.94 88.27,67.94 87,66.67 v83.82,66.67 | v55.88,45.08 62.23,45.08 62.87,44.45 IC4./AS
  Bottom 0.254: v83.82,66.67 83.82,65.41 82.55,64.14 82.55,46.99 81.92,46.36 57.15,46.36 v55.88,45.08
N$38  (via drill 0.81 pad 1.68)
  Top 0.254: 89.78,57.78 98.42,57.78 99.06,58.42 99.06,60.96 99.69,61.59 v100.33,61.59
  Bottom 0.254: 110.49,62.86 109.22,61.59 v100.33,61.59
N$39  (via drill 0.81 pad 1.68)
  Top 0.254: IC3.5 99.69,56.52 100.33,57.15 v100.33,59.05
  Bottom 0.254: PL3. 109.22,59.05 v100.33,59.05
N$40  (via drill 0.81 pad 1.68)
  Top 0.254: 89.78,59.05 97.79,59.05 98.42,59.69 98.42,63.5 99.06,64.14 v100.33,64.14
  Bottom 0.254: 110.49,65.41 109.22,64.14 v100.33,64.14
N$41
  Top 0.254: 89.78,60.33 97.16,60.33 97.79,60.96 97.79,66.04 99.06,67.31 99.06,69.22 98.42,69.85 98.42,71.69
N$42  (via drill 0.81 pad 1.68)
  Top 0.254: 89.78,69.22 88.27,69.22 87.63,68.58 81.92,68.58 81.28,67.94 v81.28,66.67 | v54.61,47.62 53.98,46.99 53.98,43.81 54.61,43.18 64.01,43.18
  Bottom 0.254: v81.28,66.67 81.28,48.26 80.64,47.62 v54.61,47.62
N$43  (via drill 0.81 pad 1.68)
  Top 0.254: 50.16,73.56 50.16,75.56 50.8,76.2 v50.8,81.28
  Bottom 0.254: 49.53,87.63 50.16,87.63 50.8,87 v50.8,81.28
N$44  (via drill 0.81 pad 1.68)
  Top 0.254: 89.78,64.14 88.27,64.14 86.36,62.23 v77.47,62.23 | 34.92,25.4 v38.1,25.4 | 34.92,25.4 R24. | 29.27,25.4 34.92,25.4
  Bottom 0.254: v77.47,62.23 77.47,50.17 76.84,49.53 46.99,49.53 46.36,48.89 46.36,41.27 49.53,38.1 51.44,38.1 52.07,37.47 52.07,33.66 51.44,33.02 38.73,33.02 38.1,32.38 v38.1,25.4
N$45  (via drill 0.81 pad 1.68)
  Top 0.254: 89.78,61.59 88.27,61.59 87.63,60.96 80.64,60.96 v79.38,59.69 | R25. v30.48,21.59 30.48,24.13 29.27,24.13
  Bottom 0.254: v79.38,59.69 79.38,49.53 78.74,48.89 47.62,48.89 46.99,48.26 46.99,41.91 49.53,39.37 52.7,39.37 53.34,38.73 53.34,32.38 52.7,31.75 40.64,31.75 40,31.11 40,22.23 39.37,21.59 v30.48,21.59
N$46  (via drill 0.81 pad 1.68)
  Top 0.254: 88.27,70.72 88.27,76.2 88.9,76.84 v90.17,76.84 | 64.01,41.91 59.05,41.91 v57.15,40
  Bottom 0.254: v90.17,76.84 90.17,41.91 89.53,41.27 61.59,41.27 60.96,41.91 59.05,41.91 v57.15,40
N$47  (via drill 0.81 pad 1.68)
  Top 0.254: IC3.7 87,73.03 87.63,73.66 87.63,76.84 89.53,78.74 v91.44,78.74 | 64.01,40.64 63.5,40.64 62.87,40 v59.69,40
  Bottom 0.254: v91.44,78.74 92.08,78.11 92.08,74.93 91.44,74.3 91.44,40.64 90.81,40 v59.69,40
N$48  (via drill 0.81 pad 1.68)
  Top 0.254: 89.78,65.41 92.08,65.41 93.34,64.14 v95.89,64.14 | IC4./ 79.38,31.75 80.64,30.48 80.64,26.04 81.28,25.4 93.98,25.4 94.61,26.04 94.61,36.2 v95.25,36.83
  Bottom 0.254: v95.89,64.14 93.98,64.14 93.34,63.5 93.34,50.8 95.25,48.89 v95.25,36.83
N$49  (via drill 0.81 pad 1.68)
  Top 0.254: v100.97,79.38 100.97,76.89
  Bottom 0.254: v100.97,79.38 100.97,73.66 101.6,73.03 108.58,73.03 109.22,72.39 109.22,66.67 107.95,65.41
N$50  (via drill 0.81 pad 1.68)
  Top 0.254: v97.16,68.58 IC7. | v56.52,32.38 52.7,32.38 52.07,33.02 52.07,38.73 50.8,40 50.8,42.55 51.44,43.18 51.44,54.61 50.16,55.88 44.45,55.88 43.81,56.52 43.81,67.41 | v76.84,33.02 74.3,33.02 v76.84,33.02
  Bottom 0.254: v97.16,68.58 97.16,46.99 97.79,46.36 97.79,34.29 97.16,33.66 77.47,33.66 v76.84,33.02 57.15,33.02 v56.52,32.38
N$51  (via drill 0.81 pad 1.68)
  Top 0.254: IC4.L2 63.5,35.56 62.87,34.92 v59.69,34.92 | 88.27,35.56 88.27,37.47 87.63,38.1 Q1. | 89.53,35.23 88.59,35.23 88.27,35.56 | 88.27,35.56 88.27,38.73 90.81,38.73 91.44,38.1 v91.44,37.47
  Bottom 0.254: v59.69,34.92 90.81,34.92 91.44,35.56 v91.44,37.47
N$52  (via drill 0.81 pad 1.68)
  Top 0.254: IC4.L1 63.5,36.83 62.87,36.2 60.96,36.2 60.33,36.83 57.78,36.83 v57.15,36.2 | 81.92,35.23 82.86,35.23 83.19,35.56 | 83.44,38.1 83.19,38.1 83.19,35.56 | 83.19,35.56 83.19,38.73 81.28,38.73 80.64,38.1 v80.64,37.47
  Bottom 0.254: v57.15,36.2 57.78,36.83 60.33,36.83 60.96,36.2 80.01,36.2 80.64,36.83 v80.64,37.47
N$54
  Top 0.254: 58.42,53.34 58.22,53.34 57.78,53.34 57.78,55.25 58.67,56.13 58.7,56.13
N$55
  Top 0.254: 74.3,35.56 76.2,35.56 79.38,32.38 80.01,32.38 81.28,31.11 81.28,26.67 81.92,26.04 93.34,26.04 93.98,26.67 93.98,34.29 93.34,34.92 93.34,40 93.98,40.64 99.69,40.64 99.69,41.97
N$56
  Bottom 0.254: 46.99,65.41 46.79,65.41 R36.
N$57
  Bottom 0.254: 46.99,73.03 46.79,73.03 R38.
N$58
  Bottom 0.254: R40. 46.79,70.48
N$59
  Bottom 0.254: 46.99,67.94 46.79,67.94 R42.
N$60
  Bottom 0.254: 90.81,85.09 90.81,80.64 88.27,78.11 74.3,78.11 71.75,75.56 71.75,55.25 70.48,53.97 66.83,53.97
N$61  (via drill 0.81 pad 1.68)
  Top 0.254: v100.97,48.26 v93.34,48.26
  Bottom 0.254: 111.12,24.13 110.49,24.77 97.79,24.77 97.16,25.4 97.16,30.48 104.14,30.48 104.78,31.11 104.78,38.73 105.41,39.37 107.31,39.37 107.95,40 107.95,43.81 107.31,44.45 102.23,44.45 101.6,45.08 101.6,47.62 v100.97,48.26 | PL2. 92.08,86.36 92.08,81.92 92.71,81.28 92.71,48.89 v93.34,48.26
N$63
  Top 0.254: 104.14,29.64 104.14,29.84 102.23,29.84 101.6,30.48 | 103.5,36.77 103.5,34.92 102.87,34.29 100.33,34.29 99.69,33.66 99.69,30.48 100.33,29.84 100.97,29.84 101.6,30.48 | SJ1. 101.6,30.48
N$64
  Bottom 0.254: D7. 34.92,68.58 R10.
N$65  (via drill 0.81 pad 1.68)
  Top 0.254: v104.14,26.67 105.41,26.67 106.05,27.3 106.05,29.21 106.68,29.84 R3.
  Bottom 0.254: JP3. 111.12,29.21 110.49,28.57 104.78,28.57 104.14,27.94 v104.14,26.67
N$67
  Bottom 0.254: D8. 37.47,68.58 R11.
N$68
  Bottom 0.254: 22.23,64.29 22.23,62.86 20.95,61.59 20.95,59.75 20.95,59.69
N$69  (via drill 0.81 pad 1.68)
  Top 0.254: v56.52,76.2 54.61,76.2 53.98,75.56 v53.98,73.03
  Bottom 0.254: R39. 49.53,73.03 49.53,74.3 50.16,74.93 53.34,74.93 54.61,76.2 v56.52,76.2 60.96,76.2 64.77,80.01 68.58,80.01 70.48,81.92 81.92,81.92 84.45,84.45 84.45,86.36 85.72,87.63 | 66.83,64.14 64.13,64.14 63.5,64.77 63.5,69.85 62.23,71.12 54.61,71.12 53.98,71.75 v53.98,73.03
N$70
  Top 0.254: 66.04,68.25 64.13,70.16 64.13,72.39 Q2. 64.13,72.77 64.13,80.01 64.77,80.64 83.82,80.64 84.45,80.01 IC3.L1
N$71
  Bottom 0.254: 24.77,59.69 24.77,59.75 24.77,64.29
N$72
  Bottom 0.254: 27.3,59.69 27.3,59.75 27.3,64.29
N$73
  Bottom 0.254: 29.84,64.29 29.84,62.86 31.12,61.59 31.12,59.75 31.12,59.69
N$74
  Bottom 0.254: 32.39,64.29 32.39,63.5 33.66,62.23 33.66,59.75 33.66,59.69
N$75
  Bottom 0.254: 34.92,64.29 34.92,62.86 35.56,62.23 36.83,62.23 37.47,61.59 37.47,59.75 37.47,59.69
N$76  (via drill 0.81 pad 1.68)
  Top 0.254: 25.4,44.98 25.4,46.99 v26.67,48.26 27.3,47.62 33.02,47.62 33.66,46.99 R12.
  Bottom 0.254: 18.41,54.55 18.41,46.36 19.05,45.72 26.04,45.72 26.67,46.36 v26.67,48.26
N$77
  Bottom 0.254: 37.47,64.29 37.47,62.86 38.1,62.23 39.37,62.23 40,61.59 40,59.75 40,59.69
N$78  (via drill 0.81 pad 1.68)
  Top 0.254: v69.85,78.74 68.58,78.74 67.94,78.11 v67.94,73.66
  Bottom 0.254: 85.72,85.09 85.72,84.45 82.55,81.28 72.39,81.28 v69.85,78.74 | 66.83,55.25 70.48,55.25 71.12,55.88 71.12,69.22 67.94,72.39 v67.94,73.66
N$79  (via drill 0.81 pad 1.68)
  Top 0.254: 88.27,55 101.36,55 102.23,55.88 v102.23,62.86
  Bottom 0.254: v102.23,62.86 107.95,62.86
N$80  (via drill 0.81 pad 1.68)
  Top 0.254: 24.13,44.98 v24.13,47.62 24.13,48.89 24.77,49.53 27.94,49.53 29.21,48.26 34.92,48.26 36.2,46.99 R13.
  Bottom 0.254: v24.13,47.62 20.32,47.62 19.68,48.26 19.68,51.44 20.95,52.7 20.95,54.55
N$81
  Bottom 0.254: 88.27,87.63 87,86.36 87,84.45 83.19,80.64 74.3,80.64 70.48,76.84 68.58,76.84 66.67,78.74 64.77,78.74 62.87,76.84 62.87,74.3 | 66.83,65.41 64.77,65.41 64.13,66.04 64.13,70.48 62.87,71.75 62.87,74.3 | R41. 50.8,70.48 51.44,71.12 51.44,73.66 52.07,74.3 62.87,74.3
N$82
  Bottom 0.254: 19.68,64.29 19.68,63.5 18.41,62.23 18.41,59.75 18.41,59.69
N$83  (via drill 0.81 pad 1.68)
  Top 0.254: 22.86,44.98 v22.86,50.17 28.57,50.17 29.84,48.89 35.56,48.89 36.2,48.26 39.37,48.26 40,47.62 R14. 40,46.36
  Bottom 0.254: 24.77,54.55 24.77,50.8 24.13,50.17 v22.86,50.17
N$84  (via drill 0.81 pad 1.68)
  Top 0.254: 48.9,73.56 48.9,75.56 48.26,76.2 v48.26,81.28
  Bottom 0.254: 46.99,87.63 47.62,87.63 48.26,87 v48.26,81.28
N$85  (via drill 0.81 pad 1.68)
  Top 0.254: 21.59,44.98 21.59,48.26 20.95,48.89 20.95,51.44 21.59,52.07 v27.3,52.07 27.94,52.07 30.48,49.53 36.2,49.53 36.83,48.89 41.91,48.89 42.55,48.26 R15. 42.55,46.36
  Bottom 0.254: v27.3,52.07 27.3,54.55
N$86  (via drill 0.81 pad 1.68)
  Top 0.254: v69.85,75.56 69.85,69.85 68.58,68.58 68.58,61.59 67.31,60.33 58.42,60.33 56.52,62.23 53.98,62.23 53.34,61.59 v53.34,60.33
  Bottom 0.254: 90.81,87.63 89.53,86.36 89.53,80.64 87.63,78.74 73.66,78.74 71.12,76.2 69.85,76.2 | 48.26,67.31 48.26,63.5 | 67.31,66.67 67.94,67.31 67.94,68.58 64.13,72.39 64.13,76.84 64.77,77.47 66.67,77.47 67.94,76.2 69.85,76.2 | v69.85,75.56 69.85,76.2 | R43. 48.9,67.94 48.26,67.31 | 48.26,67.31 48.26,62.23 50.16,60.33 v53.34,60.33
  Bottom 0.406: 67.31,66.67 IC12.
N$87  (via drill 0.81 pad 1.68)
  Top 0.254: 21.59,38.84 21.59,37.47 22.86,36.2 22.86,34.29 23.5,33.66 42.55,33.66 43.18,34.29 43.18,38.73 | v43.81,41.27 43.18,40.64 43.18,38.73 | 43.18,38.73 R16. | v31.12,52.07 31.75,52.7 v45.72,52.7
  Bottom 0.254: v45.72,52.7 45.72,51.44 44.45,50.17 44.45,41.91 v43.81,41.27 | v31.12,52.07 31.12,54.55
N$88  (via drill 0.81 pad 1.68)
  Top 0.254: 47.62,73.56 47.62,75.56 45.72,77.47 v45.72,81.28
  Bottom 0.254: 44.45,87.63 45.09,87.63 45.72,87 v45.72,81.28
N$89  (via drill 0.81 pad 1.68)
  Top 0.254: 22.86,38.84 22.86,38.1 23.5,37.47 23.5,34.92 24.13,34.29 40.64,34.29 41.27,34.92 41.27,36.2 R17. 41.91,36.2 41.91,40.64 v41.27,41.27 | v43.81,51.44 v33.66,51.44
  Bottom 0.254: v43.81,51.44 43.81,43.18 43.18,42.55 41.91,42.55 41.27,41.91 v41.27,41.27 | v33.66,51.44 33.66,54.55
N$90  (via drill 0.81 pad 1.68)
  Top 0.254: 46.36,73.56 46.36,75.56 45.09,76.84 43.81,76.84 43.18,77.47 v43.18,81.28
  Bottom 0.254: 41.91,87.63 42.55,87.63 43.18,87 v43.18,81.28
N$91  (via drill 0.81 pad 1.68)
  Top 0.254: 24.13,38.84 24.13,36.2 24.77,35.56 33.02,35.56 33.02,36.2 | v36.83,41.27 36.2,41.27 34.92,40 34.92,36.83 34.29,36.2 33.02,36.2 | v41.91,50.17 v37.47,50.17 | 33.02,36.2 R18.
  Bottom 0.254: v41.91,50.17 41.91,43.81 41.27,43.18 37.47,43.18 36.83,42.55 v36.83,41.27 | v37.47,50.17 37.47,54.55
N$92  (via drill 0.81 pad 1.68)
  Top 0.254: 45.09,73.56 45.09,75.56 44.45,76.2 41.27,76.2 40.64,76.84 v40.64,81.28
  Bottom 0.254: 39.37,87.63 40,87.63 40.64,87 v40.64,81.28
N$93  (via drill 0.81 pad 1.68)
  Top 0.254: 25.4,38.84 25.4,36.83 26.04,36.2 31.12,36.2 32.39,37.47 32.39,38.1 33.02,38.73 R19. 33.45,41.07 v33.66,41.27
  Bottom 0.254: v33.66,41.27 33.66,43.81 34.29,44.45 38.73,44.45 39.37,45.08 39.37,52.07 40,52.7 40,54.55 40,54.61
N$94  (via drill 0.81 pad 1.68)
  Top 0.254: 43.81,73.56 43.81,74.93 43.18,75.56 38.73,75.56 38.1,76.2 v38.1,81.28
  Bottom 0.254: 36.83,87.63 37.47,87.63 38.1,87 v38.1,81.28
N$95
  Bottom 0.254: 37.47,73.86 37.47,75.56 38.1,76.2 50.8,76.2 54.61,80.01 54.61,85.09
N$96
  Bottom 0.254: 46.99,85.09 46.99,80.01 45.09,78.11 30.48,78.11 29.84,77.47 29.84,73.86 29.84,73.66
N$98  (via drill 0.81 pad 1.68)
  Top 0.254: v88.27,48.89 88.27,51.44 87,52.7 87,55 | 48.9,67.41 48.9,66.04 46.36,63.5 46.36,60.96 46.99,60.33 49.53,60.33 50.16,59.69 50.16,57.15 52.07,55.25 v52.07,41.27
  Bottom 0.254: v88.27,48.89 88.27,43.18 87.63,42.55 58.42,42.55 57.78,41.91 52.7,41.91 v52.07,41.27
N$102
  Top 0.254: 76.84,55.25 IC3.2 76.84,43.18 | 76.84,43.18 74.3,43.18 | 76.84,43.18 71.12,43.18 70.48,42.55 70.48,26.24
N$104
  Top 0.254: 76.2,44.45 76.2,49.53 75.56,50.17 IC3.3 | 76.2,44.45 74.3,44.45 | 76.2,44.45 70.48,44.45 69.85,43.81 69.85,27.94 68.58,27.94 67.94,27.3 67.94,26.24 67.94,26.04
N$105
  Top 0.254: IC3.4 74.3,56.52 74.3,50.17 75.56,48.89 75.56,45.72 | 75.56,45.72 74.3,45.72 | 75.56,45.72 69.85,45.72 69.22,45.08 69.22,28.57 66.04,28.57 65.41,27.94 65.41,26.24 65.41,26.04
N$106
  Top 0.254: 60.96,47.42 60.96,46.99 64.01,46.99 67.94,46.99 71.12,50.17 71.12,57.78 72.39,59.05 IC3.6
N$108
  Bottom 0.254: 44.45,85.09 44.45,80.01 43.18,78.74 27.94,78.74 27.3,78.11 27.3,73.86 27.3,73.66
N$110
  Bottom 0.254: 49.53,85.09 49.53,80.01 46.99,77.47 33.02,77.47 32.39,76.84 32.39,73.86 32.39,73.66
N$112
  Bottom 0.254: 52.07,85.09 52.07,80.01 48.9,76.84 35.56,76.84 34.92,76.2 34.92,73.86 34.92,73.66

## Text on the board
text: BASE | <OPTO | SENS> | 8/2002 | PROG | CAN | R120 | GND | +12V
